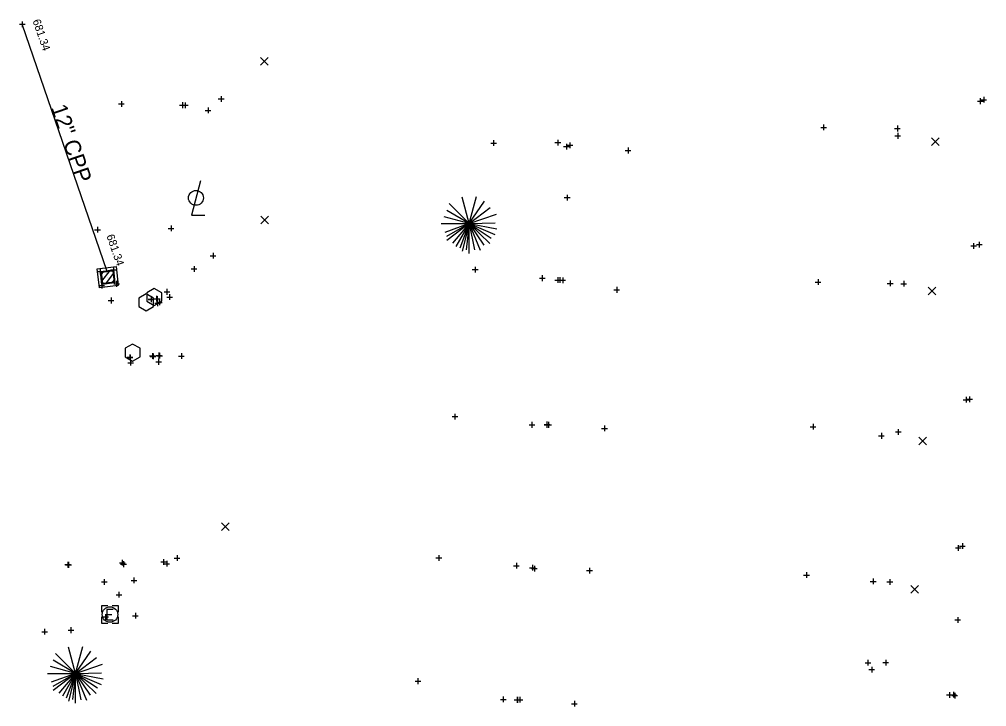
# Model space of a CAD drawing. Extents: x 2188719 to 2189819, y 654569 to 659504.
# Drawn here: x 2189638.3 to 2189807.6, y 657368.9 to 657489.2 of the extents above; entities that cross this region are included whole.
import ezdxf

# ---------------------------------------------------------------- set-up
doc = ezdxf.new("R2010")
doc.units = 0
for name, color, linetype in [('DR_X_Cells', 7, 'Continuous'), ('DR_X_Elev_Flow', 7, 'Continuous'), ('DR_X_Storm_Sewer', 7, 'Continuous'), ('DR_X_Text', 7, 'Continuous'), ('GK_Drainage_Nodes', 7, 'Continuous'), ('LT_X_Poles', 7, 'Continuous'), ('RD_X_Cells', 7, 'Continuous'), ('SC_Scratch1', 7, 'Continuous'), ('SV_X_Random_Point', 7, 'Continuous'), ('SV_X_Shot_Marker', 7, 'Continuous'), ('UT_X_Electric_Cells', 7, 'Continuous'), ('VG_X_Cells', 7, 'Continuous')]:
    doc.layers.add(name, color=color, linetype=linetype)

msp = doc.modelspace()

# ---------------------------------------------------------------- linework, layer by layer
at = {"layer": 'DR_X_Cells'}
for p, q in [((2189652.61, 657444.42), (2189653.16, 657445.11)), ((2189652.74, 657443.29), (2189654.28, 657445.24)), ((2189653.4, 657442.83), (2189654.88, 657444.71)), ((2189654.52, 657442.96), (2189655.01, 657443.58))]:
    msp.add_line(p, q, dxfattribs=at)
for points in [[(2189651.96, 657445.5), (2189655.27, 657445.88), (2189655.65, 657442.57), (2189652.34, 657442.19)], [(2189652.54, 657445.04), (2189654.81, 657445.3), (2189655.08, 657443.03), (2189652.8, 657442.76)], [(2189652.7, 657444.91), (2189654.69, 657445.14), (2189654.92, 657443.15), (2189652.93, 657442.92)]]:
    msp.add_lwpolyline(points, close=True, dxfattribs=at)
at = {"layer": 'DR_X_Elev_Flow'}
for p, q in [((2189638.85, 657488.8), (2189638.85, 657487.8)), ((2189638.35, 657488.3), (2189639.35, 657488.3)), ((2189638.85, 657488.3), (2189638.85, 657488.3))]:
    msp.add_line(p, q, dxfattribs=at)
at = {"layer": 'DR_X_Storm_Sewer'}
msp.add_line((2189653.69, 657445.03), (2189638.85, 657488.3), dxfattribs=at)
at = {"layer": 'GK_Drainage_Nodes'}
for p, q in [((2189653.62, 657445.69), (2189653.62, 657445.69)), ((2189653.69, 657445.03), (2189653.69, 657445.03)), ((2189652.81, 657443.92), (2189652.81, 657443.92)), ((2189653.81, 657444.03), (2189653.81, 657444.03)), ((2189653.81, 657444.03), (2189653.81, 657444.03)), ((2189653.81, 657444.03), (2189653.81, 657444.03)), ((2189654.8, 657444.15), (2189654.8, 657444.15)), ((2189653.92, 657443.04), (2189653.92, 657443.04)), ((2189654, 657442.38), (2189654, 657442.38))]:
    msp.add_line(p, q, dxfattribs=at)
at = {"layer": 'LT_X_Poles'}
msp.add_lwpolyline([(2189670.02, 657460.87), (2189668.45, 657454.89), (2189670.81, 657454.89)], dxfattribs=at)
msp.add_circle((2189669.24, 657457.92), 1.3, dxfattribs=at)
at = {"layer": 'RD_X_Cells'}
for points in [[(2189660.65, 657439.81), (2189661.95, 657439.06), (2189663.25, 657439.81), (2189663.25, 657441.31), (2189661.95, 657442.06), (2189660.65, 657441.31), (2189660.65, 657439.81)], [(2189659.23, 657438.89), (2189660.52, 657438.14), (2189661.82, 657438.89), (2189661.82, 657440.39), (2189660.52, 657441.14), (2189659.23, 657440.39), (2189659.23, 657438.89)], [(2189656.86, 657430.09), (2189658.16, 657429.34), (2189659.46, 657430.09), (2189659.46, 657431.59), (2189658.16, 657432.34), (2189656.86, 657431.59), (2189656.86, 657430.09)]]:
    msp.add_lwpolyline(points, dxfattribs=at)
at = {"layer": 'SV_X_Random_Point'}
for p, q in [((2189680.54, 657481.15), (2189681.87, 657482.48)), ((2189680.54, 657482.48), (2189681.87, 657481.15)), ((2189797.94, 657467.09), (2189799.27, 657468.43)), ((2189797.94, 657468.43), (2189799.27, 657467.09)), ((2189680.6, 657453.39), (2189681.93, 657454.72)), ((2189680.6, 657454.72), (2189681.93, 657453.39)), ((2189797.34, 657440.93), (2189798.68, 657442.27)), ((2189797.34, 657442.27), (2189798.68, 657440.93)), ((2189795.72, 657414.68), (2189797.05, 657416.01)), ((2189795.72, 657416.01), (2189797.05, 657414.68)), ((2189673.71, 657399.7), (2189675.04, 657401.03)), ((2189673.71, 657401.03), (2189675.04, 657399.7)), ((2189794.29, 657388.73), (2189795.62, 657390.07)), ((2189794.29, 657390.07), (2189795.62, 657388.73))]:
    msp.add_line(p, q, dxfattribs=at)
at = {"layer": 'SV_X_Shot_Marker'}
for p, q in [((2189673.65, 657475.72), (2189673.65, 657474.72)), ((2189806.44, 657475.34), (2189806.44, 657474.34)), ((2189807.06, 657475.58), (2189807.06, 657474.58)), ((2189655.69, 657474.35), (2189656.69, 657474.35)), ((2189656.19, 657474.85), (2189656.19, 657473.85)), ((2189656.19, 657474.35), (2189656.19, 657474.35)), ((2189666.39, 657474.14), (2189667.39, 657474.14)), ((2189666.39, 657474.14), (2189667.39, 657474.14)), ((2189666.87, 657474.12), (2189667.87, 657474.12)), ((2189666.89, 657474.64), (2189666.89, 657473.64)), ((2189666.89, 657474.64), (2189666.89, 657473.64)), ((2189666.89, 657474.14), (2189666.89, 657474.14)), ((2189666.89, 657474.14), (2189666.89, 657474.14)), ((2189667.37, 657474.62), (2189667.37, 657473.62)), ((2189667.37, 657474.12), (2189667.37, 657474.12)), ((2189671.37, 657473.72), (2189671.37, 657472.72)), ((2189671.37, 657473.72), (2189671.37, 657472.72)), ((2189673.15, 657475.22), (2189674.15, 657475.22)), ((2189673.65, 657475.22), (2189673.65, 657475.22)), ((2189805.94, 657474.84), (2189806.94, 657474.84)), ((2189806.44, 657474.84), (2189806.44, 657474.84)), ((2189806.56, 657475.08), (2189807.56, 657475.08)), ((2189807.06, 657475.08), (2189807.06, 657475.08)), ((2189670.87, 657473.22), (2189671.87, 657473.22)), ((2189670.87, 657473.22), (2189671.87, 657473.22)), ((2189671.37, 657473.22), (2189671.37, 657473.22)), ((2189671.37, 657473.22), (2189671.37, 657473.22)), ((2189778.53, 657470.26), (2189779.53, 657470.26)), ((2189779.03, 657470.76), (2189779.03, 657469.76)), ((2189779.03, 657470.26), (2189779.03, 657470.26)), ((2189791.95, 657470.56), (2189791.95, 657469.56)), ((2189791.45, 657470.06), (2189792.45, 657470.06)), ((2189791.52, 657468.77), (2189792.52, 657468.77)), ((2189791.95, 657470.06), (2189791.95, 657470.06)), ((2189792.02, 657469.27), (2189792.02, 657468.27)), ((2189792.02, 657468.77), (2189792.02, 657468.77)), ((2189720.8, 657467.5), (2189721.8, 657467.5)), ((2189721.3, 657468), (2189721.3, 657467)), ((2189721.3, 657467.5), (2189721.3, 657467.5)), ((2189732.05, 657467.6), (2189733.05, 657467.6)), ((2189732.55, 657468.1), (2189732.55, 657467.1)), ((2189732.55, 657467.6), (2189732.55, 657467.6)), ((2189733.56, 657466.89), (2189734.56, 657466.89)), ((2189734.06, 657467.39), (2189734.06, 657466.39)), ((2189734.06, 657466.89), (2189734.06, 657466.89)), ((2189734.15, 657467.13), (2189735.15, 657467.13)), ((2189734.65, 657467.63), (2189734.65, 657466.63)), ((2189734.65, 657467.13), (2189734.65, 657467.13)), ((2189744.34, 657466.21), (2189745.34, 657466.21)), ((2189744.84, 657466.71), (2189744.84, 657465.71)), ((2189744.84, 657466.21), (2189744.84, 657466.21)), ((2189734.18, 657458.47), (2189734.18, 657457.47)), ((2189733.68, 657457.97), (2189734.68, 657457.97)), ((2189734.18, 657457.97), (2189734.18, 657457.97)), ((2189651.52, 657452.34), (2189652.52, 657452.34)), ((2189652.02, 657452.84), (2189652.02, 657451.84)), ((2189652.02, 657452.34), (2189652.02, 657452.34)), ((2189664.38, 657452.57), (2189665.38, 657452.57)), ((2189664.88, 657453.07), (2189664.88, 657452.07)), ((2189664.88, 657452.57), (2189664.88, 657452.57)), ((2189805.27, 657450), (2189805.27, 657449)), ((2189806.26, 657450.23), (2189806.26, 657449.23)), ((2189672.23, 657448.28), (2189672.23, 657447.28)), ((2189804.77, 657449.5), (2189805.77, 657449.5)), ((2189805.27, 657449.5), (2189805.27, 657449.5)), ((2189805.76, 657449.73), (2189806.76, 657449.73)), ((2189806.26, 657449.73), (2189806.26, 657449.73)), ((2189671.73, 657447.78), (2189672.73, 657447.78)), ((2189672.23, 657447.78), (2189672.23, 657447.78)), ((2189651.99, 657445.02), (2189652.99, 657445.02)), ((2189652.49, 657445.52), (2189652.49, 657444.52)), ((2189652.49, 657445.02), (2189652.49, 657445.02)), ((2189654.29, 657445.33), (2189655.29, 657445.33)), ((2189654.79, 657445.83), (2189654.79, 657444.83)), ((2189654.79, 657445.33), (2189654.79, 657445.33)), ((2189668.42, 657445.48), (2189669.42, 657445.48)), ((2189668.42, 657445.48), (2189669.42, 657445.48)), ((2189668.92, 657445.98), (2189668.92, 657444.98)), ((2189668.92, 657445.98), (2189668.92, 657444.98)), ((2189668.92, 657445.48), (2189668.92, 657445.48)), ((2189668.92, 657445.48), (2189668.92, 657445.48)), ((2189717.59, 657445.37), (2189718.59, 657445.37)), ((2189718.09, 657445.87), (2189718.09, 657444.87)), ((2189718.09, 657445.37), (2189718.09, 657445.37)), ((2189655.37, 657443.37), (2189655.37, 657442.37)), ((2189729.32, 657443.86), (2189730.32, 657443.86)), ((2189729.82, 657444.36), (2189729.82, 657443.36)), ((2189729.82, 657443.86), (2189729.82, 657443.86)), ((2189732.02, 657443.52), (2189733.02, 657443.52)), ((2189732.42, 657443.54), (2189733.42, 657443.54)), ((2189732.52, 657444.02), (2189732.52, 657443.02)), ((2189732.52, 657443.52), (2189732.52, 657443.52)), ((2189732.9, 657443.5), (2189733.9, 657443.5)), ((2189732.92, 657444.04), (2189732.92, 657443.04)), ((2189732.92, 657443.54), (2189732.92, 657443.54)), ((2189733.4, 657444), (2189733.4, 657443)), ((2189733.4, 657443.5), (2189733.4, 657443.5)), ((2189777.58, 657443.18), (2189778.58, 657443.18)), ((2189778.08, 657443.68), (2189778.08, 657442.68)), ((2189778.08, 657443.18), (2189778.08, 657443.18)), ((2189790.68, 657443.44), (2189790.68, 657442.44)), ((2189793.07, 657443.39), (2189793.07, 657442.39)), ((2189652.27, 657442.57), (2189653.27, 657442.57)), ((2189652.77, 657443.07), (2189652.77, 657442.07)), ((2189652.77, 657442.57), (2189652.77, 657442.57)), ((2189654.87, 657442.87), (2189655.87, 657442.87)), ((2189655.37, 657442.87), (2189655.37, 657442.87)), ((2189663.67, 657441.47), (2189664.67, 657441.47)), ((2189664.17, 657441.97), (2189664.17, 657440.97)), ((2189664.17, 657441.47), (2189664.17, 657441.47)), ((2189742.36, 657441.82), (2189743.36, 657441.82)), ((2189742.86, 657442.32), (2189742.86, 657441.32)), ((2189742.86, 657441.82), (2189742.86, 657441.82)), ((2189790.18, 657442.94), (2189791.18, 657442.94)), ((2189790.68, 657442.94), (2189790.68, 657442.94)), ((2189792.57, 657442.89), (2189793.57, 657442.89)), ((2189793.07, 657442.89), (2189793.07, 657442.89)), ((2189653.89, 657439.95), (2189654.89, 657439.95)), ((2189654.39, 657440.45), (2189654.39, 657439.45)), ((2189654.39, 657439.95), (2189654.39, 657439.95)), ((2189660.89, 657440.15), (2189661.89, 657440.15)), ((2189660.9, 657440.2), (2189661.9, 657440.2)), ((2189661.39, 657440.65), (2189661.39, 657439.65)), ((2189661.39, 657440.15), (2189661.39, 657440.15)), ((2189661.4, 657440.7), (2189661.4, 657439.7)), ((2189661.4, 657440.2), (2189661.4, 657440.2)), ((2189661.84, 657440.26), (2189662.84, 657440.26)), ((2189661.98, 657440.22), (2189662.98, 657440.22)), ((2189662.34, 657440.76), (2189662.34, 657439.76)), ((2189662.34, 657440.26), (2189662.34, 657440.26)), ((2189662.48, 657440.72), (2189662.48, 657439.72)), ((2189662.48, 657440.22), (2189662.48, 657440.22)), ((2189662.52, 657439.98), (2189662.52, 657438.98)), ((2189662.85, 657440.13), (2189662.85, 657439.13)), ((2189664.13, 657440.55), (2189665.13, 657440.55)), ((2189664.63, 657441.05), (2189664.63, 657440.05)), ((2189664.63, 657440.55), (2189664.63, 657440.55)), ((2189662.02, 657439.48), (2189663.02, 657439.48)), ((2189662.35, 657439.63), (2189663.35, 657439.63)), ((2189662.52, 657439.48), (2189662.52, 657439.48)), ((2189662.85, 657439.63), (2189662.85, 657439.63)), ((2189657.19, 657430.03), (2189658.19, 657430.03)), ((2189657.22, 657429.96), (2189658.22, 657429.96)), ((2189657.22, 657429.96), (2189658.22, 657429.96)), ((2189657.69, 657430.53), (2189657.69, 657429.53)), ((2189657.69, 657430.03), (2189657.69, 657430.03)), ((2189657.72, 657430.46), (2189657.72, 657429.46)), ((2189657.72, 657430.46), (2189657.72, 657429.46)), ((2189657.72, 657429.96), (2189657.72, 657429.96)), ((2189657.72, 657429.96), (2189657.72, 657429.96)), ((2189657.8, 657429.56), (2189657.8, 657428.56)), ((2189657.8, 657429.56), (2189657.8, 657428.56)), ((2189661.12, 657430.26), (2189662.12, 657430.26)), ((2189661.23, 657430.17), (2189662.23, 657430.17)), ((2189661.62, 657430.76), (2189661.62, 657429.76)), ((2189661.62, 657430.26), (2189661.62, 657430.26)), ((2189661.73, 657430.67), (2189661.73, 657429.67)), ((2189661.73, 657430.17), (2189661.73, 657430.17)), ((2189662.23, 657430.33), (2189663.23, 657430.33)), ((2189662.39, 657430.28), (2189663.39, 657430.28)), ((2189662.7, 657429.72), (2189662.7, 657428.72)), ((2189662.73, 657430.83), (2189662.73, 657429.83)), ((2189662.73, 657430.33), (2189662.73, 657430.33)), ((2189662.89, 657430.78), (2189662.89, 657429.78)), ((2189662.89, 657430.28), (2189662.89, 657430.28)), ((2189666.19, 657430.24), (2189667.19, 657430.24)), ((2189666.69, 657430.74), (2189666.69, 657429.74)), ((2189666.69, 657430.24), (2189666.69, 657430.24)), ((2189657.3, 657429.06), (2189658.3, 657429.06)), ((2189657.3, 657429.06), (2189658.3, 657429.06)), ((2189657.8, 657429.06), (2189657.8, 657429.06)), ((2189657.8, 657429.06), (2189657.8, 657429.06)), ((2189662.2, 657429.22), (2189663.2, 657429.22)), ((2189662.7, 657429.22), (2189662.7, 657429.22)), ((2189803.98, 657423.09), (2189803.98, 657422.09)), ((2189804.59, 657423.17), (2189804.59, 657422.17)), ((2189803.48, 657422.59), (2189804.48, 657422.59)), ((2189803.98, 657422.59), (2189803.98, 657422.59)), ((2189804.09, 657422.67), (2189805.09, 657422.67)), ((2189804.59, 657422.67), (2189804.59, 657422.67)), ((2189714.04, 657419.64), (2189715.04, 657419.64)), ((2189714.54, 657420.14), (2189714.54, 657419.14)), ((2189714.54, 657419.64), (2189714.54, 657419.64)), ((2189727.51, 657418.19), (2189728.51, 657418.19)), ((2189728.01, 657418.69), (2189728.01, 657417.69)), ((2189728.01, 657418.19), (2189728.01, 657418.19)), ((2189730.13, 657418.26), (2189731.13, 657418.26)), ((2189730.13, 657418.19), (2189731.13, 657418.19)), ((2189730.44, 657418.19), (2189731.44, 657418.19)), ((2189730.63, 657418.76), (2189730.63, 657417.76)), ((2189730.63, 657418.69), (2189730.63, 657417.69)), ((2189730.63, 657418.26), (2189730.63, 657418.26)), ((2189730.63, 657418.19), (2189730.63, 657418.19)), ((2189730.94, 657418.69), (2189730.94, 657417.69)), ((2189730.94, 657418.19), (2189730.94, 657418.19)), ((2189740.71, 657418.08), (2189740.71, 657417.08)), ((2189776.69, 657417.85), (2189777.69, 657417.85)), ((2189777.19, 657418.35), (2189777.19, 657417.35)), ((2189777.19, 657417.85), (2189777.19, 657417.85)), ((2189740.21, 657417.58), (2189741.21, 657417.58)), ((2189740.71, 657417.58), (2189740.71, 657417.58)), ((2189788.66, 657416.27), (2189789.66, 657416.27)), ((2189789.16, 657416.77), (2189789.16, 657415.77)), ((2189789.16, 657416.27), (2189789.16, 657416.27)), ((2189791.6, 657416.95), (2189792.6, 657416.95)), ((2189792.1, 657417.45), (2189792.1, 657416.45)), ((2189792.1, 657416.95), (2189792.1, 657416.95)), ((2189803.33, 657397.48), (2189803.33, 657396.48)), ((2189802.1, 657396.66), (2189803.1, 657396.66)), ((2189802.6, 657397.16), (2189802.6, 657396.16)), ((2189802.6, 657396.66), (2189802.6, 657396.66)), ((2189802.83, 657396.98), (2189803.83, 657396.98)), ((2189803.33, 657396.98), (2189803.33, 657396.98)), ((2189646.82, 657394.23), (2189646.82, 657393.23)), ((2189646.9, 657394.19), (2189646.9, 657393.19)), ((2189646.97, 657394.19), (2189646.97, 657393.19)), ((2189655.86, 657394.05), (2189656.86, 657394.05)), ((2189655.86, 657394.05), (2189656.86, 657394.05)), ((2189656.36, 657394.55), (2189656.36, 657393.55)), ((2189656.36, 657394.55), (2189656.36, 657393.55)), ((2189656.36, 657394.05), (2189656.36, 657394.05)), ((2189656.36, 657394.05), (2189656.36, 657394.05)), ((2189656.57, 657394.31), (2189656.57, 657393.31)), ((2189663.08, 657394.2), (2189664.08, 657394.2)), ((2189663.58, 657394.7), (2189663.58, 657393.7)), ((2189663.58, 657394.2), (2189663.58, 657394.2)), ((2189664.13, 657394.39), (2189664.13, 657393.39)), ((2189664.13, 657394.39), (2189664.13, 657393.39)), ((2189665.43, 657394.88), (2189666.43, 657394.88)), ((2189665.93, 657395.38), (2189665.93, 657394.38)), ((2189665.93, 657394.88), (2189665.93, 657394.88)), ((2189711.23, 657394.9), (2189712.23, 657394.9)), ((2189711.73, 657395.4), (2189711.73, 657394.4)), ((2189711.73, 657394.9), (2189711.73, 657394.9)), ((2189725.3, 657394.02), (2189725.3, 657393.02)), ((2189646.32, 657393.73), (2189647.32, 657393.73)), ((2189646.4, 657393.69), (2189647.4, 657393.69)), ((2189646.47, 657393.69), (2189647.47, 657393.69)), ((2189646.82, 657393.73), (2189646.82, 657393.73)), ((2189646.9, 657393.69), (2189646.9, 657393.69)), ((2189646.97, 657393.69), (2189646.97, 657393.69)), ((2189656.07, 657393.81), (2189657.07, 657393.81)), ((2189656.57, 657393.81), (2189656.57, 657393.81)), ((2189663.63, 657393.89), (2189664.63, 657393.89)), ((2189663.63, 657393.89), (2189664.63, 657393.89)), ((2189664.13, 657393.89), (2189664.13, 657393.89)), ((2189664.13, 657393.89), (2189664.13, 657393.89)), ((2189724.8, 657393.52), (2189725.8, 657393.52)), ((2189725.3, 657393.52), (2189725.3, 657393.52)), ((2189727.59, 657393.17), (2189728.59, 657393.17)), ((2189727.63, 657393.18), (2189728.63, 657393.18)), ((2189727.94, 657393.04), (2189728.94, 657393.04)), ((2189728.09, 657393.67), (2189728.09, 657392.67)), ((2189728.09, 657393.17), (2189728.09, 657393.17)), ((2189728.13, 657393.68), (2189728.13, 657392.68)), ((2189728.13, 657393.18), (2189728.13, 657393.18)), ((2189728.44, 657393.54), (2189728.44, 657392.54)), ((2189728.44, 657393.04), (2189728.44, 657393.04)), ((2189737.59, 657392.67), (2189738.59, 657392.67)), ((2189738.09, 657393.17), (2189738.09, 657392.17)), ((2189738.09, 657392.67), (2189738.09, 657392.67)), ((2189776.05, 657392.41), (2189776.05, 657391.41)), ((2189652.71, 657390.71), (2189653.71, 657390.71)), ((2189653.21, 657391.21), (2189653.21, 657390.21)), ((2189653.21, 657390.71), (2189653.21, 657390.71)), ((2189657.88, 657390.97), (2189658.88, 657390.97)), ((2189658.38, 657391.47), (2189658.38, 657390.47)), ((2189658.38, 657390.97), (2189658.38, 657390.97)), ((2189775.55, 657391.91), (2189776.55, 657391.91)), ((2189776.05, 657391.91), (2189776.05, 657391.91)), ((2189787.21, 657390.79), (2189788.21, 657390.79)), ((2189787.71, 657391.29), (2189787.71, 657390.29)), ((2189787.71, 657390.79), (2189787.71, 657390.79)), ((2189790.13, 657390.69), (2189791.13, 657390.69)), ((2189790.63, 657391.19), (2189790.63, 657390.19)), ((2189790.63, 657390.69), (2189790.63, 657390.69)), ((2189655.77, 657388.95), (2189655.77, 657387.95)), ((2189655.27, 657388.45), (2189656.27, 657388.45)), ((2189655.77, 657388.45), (2189655.77, 657388.45)), ((2189652.92, 657384.58), (2189653.92, 657384.58)), ((2189653.42, 657385.08), (2189653.42, 657384.08)), ((2189653.42, 657384.58), (2189653.42, 657384.58)), ((2189658.14, 657384.79), (2189659.14, 657384.79)), ((2189658.64, 657385.29), (2189658.64, 657384.29)), ((2189658.64, 657384.79), (2189658.64, 657384.79)), ((2189802.01, 657384.05), (2189803.01, 657384.05)), ((2189802.51, 657384.55), (2189802.51, 657383.55)), ((2189802.51, 657384.05), (2189802.51, 657384.05)), ((2189642.77, 657382.47), (2189642.77, 657381.47)), ((2189646.88, 657382.26), (2189647.88, 657382.26)), ((2189647.38, 657382.76), (2189647.38, 657381.76)), ((2189647.38, 657382.26), (2189647.38, 657382.26)), ((2189642.27, 657381.97), (2189643.27, 657381.97)), ((2189642.77, 657381.97), (2189642.77, 657381.97)), ((2189786.29, 657376.55), (2189787.29, 657376.55)), ((2189786.79, 657377.05), (2189786.79, 657376.05)), ((2189786.79, 657376.55), (2189786.79, 657376.55)), ((2189787.46, 657375.86), (2189787.46, 657374.86)), ((2189789.42, 657376.58), (2189790.42, 657376.58)), ((2189789.92, 657377.08), (2189789.92, 657376.08)), ((2189789.92, 657376.58), (2189789.92, 657376.58)), ((2189708.07, 657373.83), (2189708.07, 657372.83)), ((2189786.96, 657375.36), (2189787.96, 657375.36)), ((2189787.46, 657375.36), (2189787.46, 657375.36)), ((2189707.57, 657373.33), (2189708.57, 657373.33)), ((2189708.07, 657373.33), (2189708.07, 657373.33)), ((2189722.99, 657370.64), (2189722.99, 657369.64)), ((2189725.42, 657370.56), (2189725.42, 657369.56)), ((2189725.5, 657370.56), (2189725.5, 657369.56)), ((2189725.92, 657370.57), (2189725.92, 657369.57)), ((2189800.55, 657370.91), (2189801.55, 657370.91)), ((2189801.05, 657371.41), (2189801.05, 657370.41)), ((2189801.05, 657370.91), (2189801.05, 657370.91)), ((2189801.27, 657370.95), (2189802.27, 657370.95)), ((2189801.49, 657370.81), (2189802.49, 657370.81)), ((2189801.77, 657371.45), (2189801.77, 657370.45)), ((2189801.77, 657370.95), (2189801.77, 657370.95)), ((2189801.99, 657371.31), (2189801.99, 657370.31)), ((2189801.99, 657370.81), (2189801.99, 657370.81)), ((2189722.49, 657370.14), (2189723.49, 657370.14)), ((2189722.99, 657370.14), (2189722.99, 657370.14)), ((2189724.92, 657370.06), (2189725.92, 657370.06)), ((2189725, 657370.06), (2189726, 657370.06)), ((2189725.42, 657370.07), (2189726.42, 657370.07)), ((2189725.42, 657370.06), (2189725.42, 657370.06)), ((2189725.5, 657370.06), (2189725.5, 657370.06)), ((2189725.92, 657370.07), (2189725.92, 657370.07)), ((2189734.94, 657369.37), (2189735.94, 657369.37)), ((2189735.44, 657369.87), (2189735.44, 657368.87)), ((2189735.44, 657369.37), (2189735.44, 657369.37))]:
    msp.add_line(p, q, dxfattribs=at)
at = {"layer": 'UT_X_Electric_Cells'}
for p, q in [((2189653.64, 657384.99), (2189654.54, 657384.99)), ((2189654.2, 657384.99), (2189654.2, 657384.99))]:
    msp.add_line(p, q, dxfattribs=at)
for points in [[(2189653.8, 657386.49), (2189652.7, 657386.49), (2189652.7, 657385.39)], [(2189654.76, 657385.89), (2189653.64, 657385.89), (2189653.64, 657384.09), (2189654.76, 657384.09)], [(2189655.7, 657385.39), (2189655.7, 657386.49), (2189654.6, 657386.49)], [(2189652.7, 657384.59), (2189652.7, 657383.49), (2189653.8, 657383.49)], [(2189654.6, 657383.49), (2189655.7, 657383.49), (2189655.7, 657384.59)]]:
    msp.add_lwpolyline(points, dxfattribs=at)
msp.add_circle((2189654.2, 657384.99), 1.35, dxfattribs=at)
at = {"layer": 'VG_X_Cells'}
for p, q in [((2189717.05, 657453.43), (2189713.56, 657456.92)), ((2189717.05, 657453.43), (2189715.81, 657458.05)), ((2189717.05, 657453.43), (2189718.31, 657458.13)), ((2189717.05, 657453.43), (2189719.71, 657457.32)), ((2189717.05, 657453.43), (2189713.14, 657455.73)), ((2189717.05, 657453.43), (2189720.71, 657456.24)), ((2189717.05, 657453.43), (2189721.79, 657455.04)), ((2189712.11, 657453.43), (2189717.05, 657453.43)), ((2189717.05, 657453.43), (2189712.64, 657454.62)), ((2189717.05, 657453.43), (2189712.76, 657451.87)), ((2189717.05, 657453.43), (2189713.07, 657451.15)), ((2189717.05, 657453.43), (2189713.14, 657450.44)), ((2189717.05, 657453.43), (2189714.1, 657449.97)), ((2189717.05, 657453.43), (2189714.73, 657449.42)), ((2189717.05, 657453.43), (2189715.38, 657449.09)), ((2189717.05, 657453.43), (2189715.79, 657448.58)), ((2189717.05, 657453.43), (2189716.51, 657448.84)), ((2189717.05, 657453.43), (2189721.56, 657453.53)), ((2189717.05, 657448.19), (2189717.05, 657453.43)), ((2189717.05, 657453.43), (2189717.97, 657448.8)), ((2189717.05, 657453.43), (2189718.98, 657448.77)), ((2189717.05, 657453.43), (2189719.59, 657449.64)), ((2189717.05, 657453.43), (2189720.64, 657449.91)), ((2189717.05, 657453.43), (2189720.87, 657450.88)), ((2189717.05, 657453.43), (2189721.52, 657451.49)), ((2189717.05, 657453.43), (2189721.88, 657452.48)), ((2189648.19, 657374.7), (2189646.95, 657379.31)), ((2189648.19, 657374.7), (2189649.44, 657379.4)), ((2189648.19, 657374.7), (2189644.69, 657378.18)), ((2189648.19, 657374.7), (2189650.84, 657378.58)), ((2189648.19, 657374.7), (2189651.84, 657377.5)), ((2189648.19, 657374.7), (2189643.77, 657375.88)), ((2189648.19, 657374.7), (2189644.28, 657376.99)), ((2189648.19, 657374.7), (2189652.92, 657376.3)), ((2189643.25, 657374.7), (2189648.19, 657374.7)), ((2189648.19, 657374.7), (2189643.9, 657373.14)), ((2189648.19, 657374.7), (2189644.2, 657372.42)), ((2189648.19, 657374.7), (2189644.28, 657371.7)), ((2189648.19, 657374.7), (2189645.24, 657371.23)), ((2189648.19, 657374.7), (2189645.87, 657370.68)), ((2189648.19, 657374.7), (2189646.52, 657370.36)), ((2189648.19, 657374.7), (2189646.92, 657369.84)), ((2189648.19, 657374.7), (2189647.64, 657370.11)), ((2189648.19, 657374.7), (2189652.69, 657374.79)), ((2189648.19, 657369.46), (2189648.19, 657374.7)), ((2189648.19, 657374.7), (2189649.11, 657370.06)), ((2189648.19, 657374.7), (2189650.12, 657370.03)), ((2189648.19, 657374.7), (2189650.72, 657370.9)), ((2189648.19, 657374.7), (2189651.77, 657371.18)), ((2189648.19, 657374.7), (2189652.01, 657372.14)), ((2189648.19, 657374.7), (2189652.65, 657372.76)), ((2189648.19, 657374.7), (2189653.01, 657373.74))]:
    msp.add_line(p, q, dxfattribs=at)

# ---------------------------------------------------------------- texts
at = {"layer": 'DR_X_Text'}
msp.add_text('12" CPP', height=2.8, rotation=288.9339, dxfattribs=at).set_placement((2189643.84, 657473.75))
at = {"layer": 'SC_Scratch1'}
for p in [(2189640.64, 657488.92), (2189653.56, 657451.28)]:
    msp.add_text('681.34', height=1.4, rotation=288.9339, dxfattribs=at).set_placement(p)

doc.saveas('drawing.dxf')
